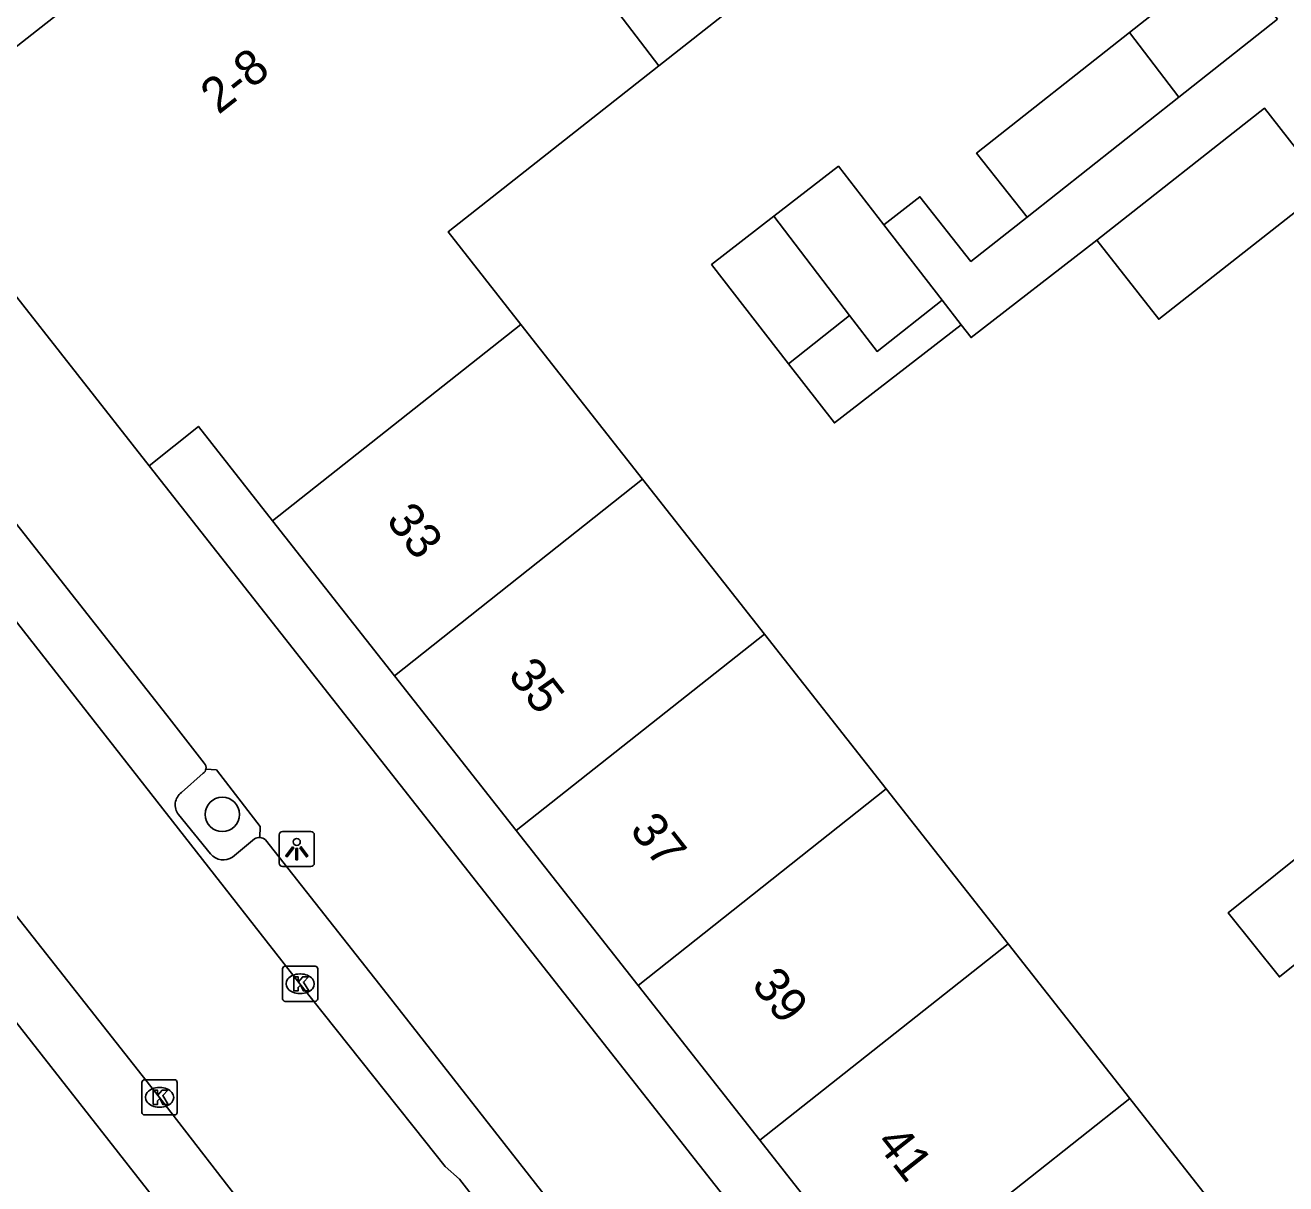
# Model space of a CAD drawing. Extents: x 160379 to 161131, y 383940 to 384849.
# Drawn here: x 160761.36 to 160797.2, y 384366.17 to 384399.1 of the extents above; entities that cross this region are included whole.
import ezdxf

# ---------------------------------------------------------------- set-up
doc = ezdxf.new("R2010")
doc.units = 0
for name, color, linetype in [('IMGEO_Boom', 7, 'Continuous'), ('IMGEO_Kolk', 7, 'Continuous'), ('IMGEO_Lichtpunt', 7, 'Continuous'), ('IMGEO_Pand', 7, 'Continuous'), ('IMGEO_Pand_nummerreeks', 7, 'Continuous'), ('IMGEO_Parkeervlak_open', 7, 'Continuous'), ('IMGEO_Rijbaan_lokaal_open', 7, 'Continuous'), ('IMGEO_Voetpad_open', 7, 'Continuous')]:
    doc.layers.add(name, color=color, linetype=linetype)

msp = doc.modelspace()

# ---------------------------------------------------------------- linework, layer by layer
at = {"layer": 'IMGEO_Boom'}
msp.add_circle((160766.961, 384376.668), 0.489, dxfattribs=at)
at = {"layer": 'IMGEO_Kolk'}
for p, q in [((160768.673, 384371.429), (160768.673, 384372.281)), ((160768.748, 384372.355), (160769.6, 384372.355)), ((160769.674, 384372.281), (160769.674, 384371.429)), ((160769.161, 384372.135), (160769.186, 384372.135)), ((160769.184, 384371.575), (160769.159, 384371.575)), ((160769.6, 384371.355), (160768.748, 384371.355)), ((160764.676, 384368.201), (160764.676, 384369.053)), ((160764.751, 384369.127), (160765.603, 384369.127)), ((160765.677, 384369.053), (160765.677, 384368.201)), ((160765.164, 384368.907), (160765.189, 384368.907)), ((160765.187, 384368.347), (160765.162, 384368.347)), ((160765.603, 384368.127), (160764.751, 384368.127))]:
    msp.add_line(p, q, dxfattribs=at)
for points in [[(160768.673, 384371.429), (160768.673, 384372.281)], [(160768.748, 384372.355), (160769.6, 384372.355)], [(160769.674, 384372.281), (160769.674, 384371.429)], [(160768.994, 384372.055), (160769.117, 384372.055), (160769.117, 384371.904), (160769.247, 384372.055), (160769.411, 384372.055), (160769.265, 384371.904), (160769.418, 384371.655), (160769.266, 384371.655), (160769.181, 384371.819), (160769.117, 384371.752), (160769.117, 384371.655), (160768.994, 384371.655), (160768.994, 384372.055)], [(160769.6, 384371.355), (160768.748, 384371.355)], [(160764.676, 384368.201), (160764.676, 384369.053)], [(160764.751, 384369.127), (160765.603, 384369.127)], [(160765.677, 384369.053), (160765.677, 384368.201)], [(160764.997, 384368.827), (160765.12, 384368.827), (160765.12, 384368.676), (160765.25, 384368.827), (160765.414, 384368.827), (160765.268, 384368.676), (160765.421, 384368.427), (160765.269, 384368.427), (160765.184, 384368.591), (160765.12, 384368.524), (160765.12, 384368.427), (160764.997, 384368.427), (160764.997, 384368.827)], [(160765.603, 384368.127), (160764.751, 384368.127)]]:
    msp.add_lwpolyline(points, dxfattribs=at)
for centre, start, end in [((160768.75, 384372.279), 91.552, 178.448), ((160768.75, 384372.279), 91.552, 178.448), ((160769.598, 384372.279), 1.552, 88.448), ((160769.598, 384372.279), 1.552, 88.448), ((160768.75, 384371.431), 181.552, 268.448), ((160768.75, 384371.431), 181.552, 268.448), ((160769.598, 384371.431), 271.552, 358.448), ((160769.598, 384371.431), 271.552, 358.448), ((160764.753, 384369.051), 91.552, 178.448), ((160764.753, 384369.051), 91.552, 178.448), ((160765.601, 384369.051), 1.552, 88.448), ((160765.601, 384369.051), 1.552, 88.448), ((160764.753, 384368.203), 181.552, 268.448), ((160764.753, 384368.203), 181.552, 268.448), ((160765.601, 384368.203), 271.552, 358.448), ((160765.601, 384368.203), 271.552, 358.448)]:
    msp.add_arc(centre, 0.0765, start, end, dxfattribs=at)
for centre, major_axis, ratio, start_param, end_param in [((160769.16, 384371.855), (-0.387, 0.002), 0.722429, 4.712389, 7.853982), ((160769.185, 384371.855), (-0.39, 0.002), 0.717154, 1.570796, 4.712389), ((160765.163, 384368.627), (-0.387, 0.002), 0.722429, 4.712389, 7.853982), ((160765.188, 384368.627), (-0.39, 0.002), 0.717154, 1.570796, 4.712389)]:
    msp.add_ellipse(centre, major_axis=major_axis, ratio=ratio, start_param=start_param, end_param=end_param, dxfattribs=at)
at = {"layer": 'IMGEO_Lichtpunt'}
for p, q in [((160769.481, 384376.183), (160768.673, 384376.183)), ((160769.481, 384376.183), (160768.673, 384376.183)), ((160768.579, 384376.088), (160768.579, 384375.281)), ((160768.579, 384376.088), (160768.579, 384375.281)), ((160769.575, 384375.281), (160769.575, 384376.088)), ((160769.575, 384375.281), (160769.575, 384376.088)), ((160768.673, 384375.187), (160769.481, 384375.187)), ((160768.673, 384375.187), (160769.481, 384375.187))]:
    msp.add_line(p, q, dxfattribs=at)
for points in [[(160768.953, 384375.752), (160768.992, 384375.724), (160768.804, 384375.462), (160768.766, 384375.489), (160768.953, 384375.752)], [(160769.055, 384375.704), (160769.102, 384375.704), (160769.102, 384375.382), (160769.055, 384375.382), (160769.055, 384375.704)], [(160769.165, 384375.724), (160769.203, 384375.751), (160769.39, 384375.489), (160769.351, 384375.461), (160769.165, 384375.724)]]:
    msp.add_lwpolyline(points, dxfattribs=at)
msp.add_circle((160769.078, 384375.886), 0.0994, dxfattribs=at)
for centre, start, end in [((160768.673, 384376.088), 90, 180), ((160768.673, 384376.088), 90, 180), ((160769.481, 384376.088), 0, 90), ((160769.481, 384376.088), 0, 90), ((160768.673, 384375.281), 180, 270), ((160768.673, 384375.281), 180, 270), ((160769.481, 384375.281), 270, 0), ((160769.481, 384375.281), 270, 360)]:
    msp.add_arc(centre, 0.0946, start, end, dxfattribs=at)
at = {"layer": 'IMGEO_Pand'}
for points in [[(160779.374, 384397.95), (160773.357, 384405.825)], [(160760.252, 384397.828), (160764.987, 384401.544)], [(160783.773, 384401.416), (160779.374, 384397.95)], [(160796.958, 384399.268), (160795.525, 384401.082), (160792.749, 384398.891)], [(160796.958, 384399.268), (160794.153, 384397.054)], [(160792.749, 384398.891), (160788.406, 384395.462), (160789.839, 384393.648)], [(160794.153, 384397.054), (160792.749, 384398.891)], [(160775.448, 384390.597), (160773.378, 384393.227), (160779.374, 384397.95)], [(160794.153, 384397.054), (160789.839, 384393.648)], [(160791.821, 384392.991), (160796.594, 384396.738), (160798.357, 384394.492)], [(160785.766, 384393.43), (160784.478, 384395.092), (160782.644, 384393.671)], [(160791.821, 384392.991), (160793.584, 384390.745), (160798.357, 384394.492)], [(160764.882, 384386.58), (160758.762, 384394.36)], [(160782.644, 384393.671), (160780.873, 384392.299), (160783.059, 384389.477)], [(160782.644, 384393.671), (160784.796, 384390.852)], [(160785.766, 384393.43), (160787.427, 384391.286)], [(160784.796, 384390.852), (160785.578, 384389.829), (160787.427, 384391.286)], [(160787.427, 384391.286), (160787.967, 384390.589)], [(160784.796, 384390.852), (160783.059, 384389.477)], [(160768.391, 384385.012), (160775.448, 384390.597)], [(160775.448, 384390.597), (160778.911, 384386.195)], [(160783.059, 384389.477), (160784.362, 384387.796), (160787.967, 384390.589)], [(160764.882, 384386.58), (160766.279, 384387.696), (160768.391, 384385.012)], [(160778.911, 384386.195), (160771.854, 384380.611)], [(160782.373, 384381.795), (160778.911, 384386.195)], [(160768.391, 384385.012), (160771.854, 384380.611)], [(160775.317, 384376.21), (160782.373, 384381.795)], [(160785.836, 384377.393), (160782.373, 384381.795)], [(160771.854, 384380.611), (160775.317, 384376.21)], [(160778.78, 384371.808), (160785.836, 384377.393)], [(160789.3, 384372.992), (160785.836, 384377.393)], [(160798.879, 384376.535), (160795.555, 384373.87), (160797.014, 384372.05), (160800.279, 384374.669)], [(160775.317, 384376.21), (160778.78, 384371.808)], [(160789.3, 384372.992), (160782.243, 384367.408)], [(160792.762, 384368.592), (160789.3, 384372.992)], [(160778.78, 384371.808), (160782.243, 384367.408)], [(160785.706, 384363.006), (160792.762, 384368.592)], [(160796.225, 384364.19), (160792.762, 384368.592)], [(160782.243, 384367.408), (160785.706, 384363.006)]]:
    msp.add_lwpolyline(points, dxfattribs=at)
at = {"layer": 'IMGEO_Parkeervlak_open'}
for points in [[(160765.8, 384377.292), (160766.419, 384377.838)], [(160766.628, 384375.546), (160765.713, 384376.665)], [(160767.874, 384375.979), (160767.254, 384375.455)]]:
    msp.add_lwpolyline(points, dxfattribs=at)
for centre, radius, start, end in [((160766.305, 384377.993), 0.193, 306.4496, 349.5396), ((160766.064, 384376.936), 0.444, 126.5795, 217.6211), ((160768.007, 384375.725), 0.287, 86.7214, 117.5206), ((160766.992, 384375.848), 0.473, 219.7279, 303.7301)]:
    msp.add_arc(centre, radius, start, end, dxfattribs=at)
at = {"layer": 'IMGEO_Rijbaan_lokaal_open'}
for points in [[(160789.695, 384345.758), (160773.707, 384366.301), (160773.293, 384366.66), (160772.415, 384367.771), (160771.935, 384368.374), (160769.169, 384371.854), (160756.891, 384387.518), (160754.3, 384390.745)], [(160785.662, 384342.471), (160783.415, 384345.455), (160773.069, 384358.615), (160769.555, 384362.982), (160769.109, 384363.537), (160768.486, 384364.333), (160767.853, 384365.154), (160765.174, 384368.627), (160752.664, 384384.48), (160750.192, 384387.495)]]:
    msp.add_lwpolyline(points, dxfattribs=at)
at = {"layer": 'IMGEO_Voetpad_open'}
for points in [[(160789.839, 384393.648), (160788.243, 384392.388), (160786.792, 384394.226), (160785.766, 384393.43)], [(160787.967, 384390.589), (160788.25, 384390.224), (160791.821, 384392.991)], [(160756.043, 384391.348), (160765.382, 384379.49), (160766.444, 384378.123)], [(160789.93, 384354.754), (160764.882, 384386.58)], [(160754.76, 384378.834), (160765.382, 384365.301)], [(160766.494, 384377.958), (160766.791, 384377.94), (160768.04, 384376.328), (160768.023, 384376.011)], [(160768.185, 384375.946), (160771.542, 384371.69), (160777.855, 384363.637), (160778.539, 384362.763)]]:
    msp.add_lwpolyline(points, dxfattribs=at)
for centre, radius, start, end in [((160766.31, 384377.992), 0.187, 349.4439, 44.2729), ((160768.001, 384375.722), 0.29, 50.5995, 85.6757)]:
    msp.add_arc(centre, radius, start, end, dxfattribs=at)

# ---------------------------------------------------------------- texts
at = {"layer": 'IMGEO_Pand_nummerreeks'}
for s, rotation, p in [('2-8', 38.1512, (160766.851, 384396.543)), ('33', 308.198, (160771.592, 384385.02)), ('35', 308.198, (160775.055, 384380.619)), ('37', 308.198, (160778.518, 384376.218)), ('39', 308.198, (160781.981, 384371.817)), ('41', 308.198, (160785.514, 384367.327))]:
    msp.add_text(s, height=1, rotation=rotation, dxfattribs=at).set_placement(p)

doc.saveas('drawing.dxf')
